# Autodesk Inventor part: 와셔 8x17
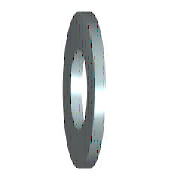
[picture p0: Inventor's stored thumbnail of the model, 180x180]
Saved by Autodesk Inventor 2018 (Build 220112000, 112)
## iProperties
Created: 2012-02
Part Number: 와셔 8x17
Material: 강철, 연강
Description: 평면 와셔
Document SubType Name: Modeling
Standard: KS B 1326
Designer: mduedu
Standards Organization: KS
Language: ko-KR
Size Designation: 8x17
Categories: <MemberInstance><Categories><Category DisplayName="조임쇠" InternalName="e4da775c-781d-43d5-af7c-5136215cf5a6" Mnemonic="FSTN"><Category DisplayName="와셔" InternalN
Density: 7.86 g/cm^3
Mass: 2.05445 g
Surface Area: 4.57416 cm^2
Volume: 0.261381 cm^3
Appearance: 파란색 - 벽 페인트 - 광택
IsCustomPart: 1
Author: mduedu
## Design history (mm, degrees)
sketch "스케치"
  geometry: C1 r 8.5 at (0, 0); C2 r 4.5 at (0, 0); 1 further point
  constraints: 2 centre point, 2 coincident
  dimensions: "d0" = 9 diameter of C2 (= SD1); "d1" = 17 diameter of C1 (= SD2)
extrude "본체" new body sketch "스케치" distance "d2" = 1.6 (= SD); taper "d3" = 0 deg
workaxis "Work Axis1"
workplane "Work Plane1"
body "Solid1"
other parameters: "SD1" = 9 [user parameter; used in 1 equation term], "SD2" = 17 [user parameter; used in 1 equation term], "SD" = 1.6 [user parameter; used in 1 equation term], "d4" = 0, "d5" = 0, "d6" = 0, "d7" = 0, "NND" = 8 [user parameter]
